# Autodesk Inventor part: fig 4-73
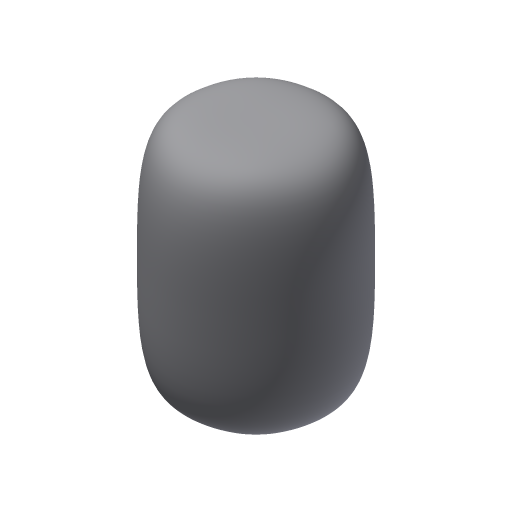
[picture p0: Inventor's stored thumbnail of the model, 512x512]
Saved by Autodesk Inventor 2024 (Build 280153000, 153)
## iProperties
Created: 2012-07
Part Number: fig 4-73
Material: Generic
Document SubType Name: Modeling
Designer: CADCIM
Density: 1 g/cm^3
Appearance: Default
Author: CADCIM
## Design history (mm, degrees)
feature "Form1"
body "Solid1"
body "Solid2"
